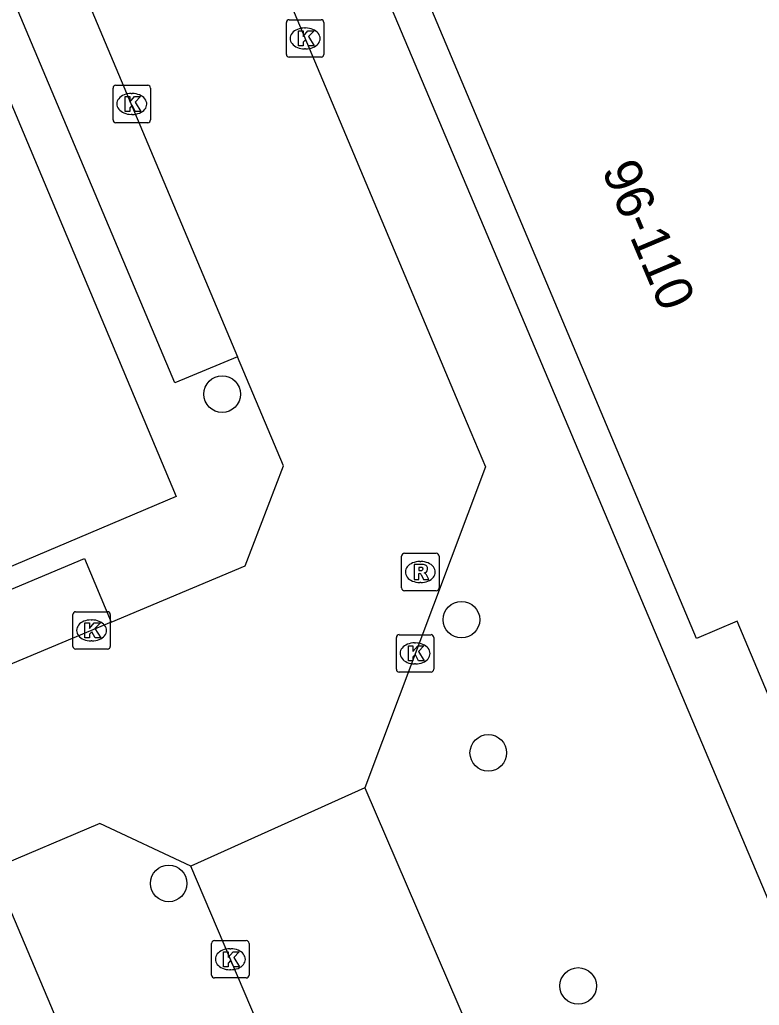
# Model space of a CAD drawing. Extents: x 157767 to 159171, y 387842 to 389425.
# Drawn here: x 158864.69 to 158884.47, y 388333.68 to 388360.03 of the extents above; entities that cross this region are included whole.
import ezdxf

# ---------------------------------------------------------------- set-up
doc = ezdxf.new("R2010")
doc.units = 0
for name, color, linetype in [('IMGEO_Boom', 7, 'Continuous'), ('IMGEO_Kolk', 7, 'Continuous'), ('IMGEO_Pand', 7, 'Continuous'), ('IMGEO_Pand_nummerreeks', 7, 'Continuous'), ('IMGEO_Rijbaan_lokaal_open', 7, 'Continuous'), ('IMGEO_Rioolput', 7, 'Continuous'), ('IMGEO_Voetpad_open', 7, 'Continuous')]:
    doc.layers.add(name, color=color, linetype=linetype)

msp = doc.modelspace()

# ---------------------------------------------------------------- linework, layer by layer
at = {"layer": 'IMGEO_Boom'}
for centre in [(158870.108, 388350.022), (158876.508, 388343.993), (158877.225, 388340.433), (158868.678, 388336.942), (158879.629, 388334.201)]:
    msp.add_circle(centre, 0.489, dxfattribs=at)
at = {"layer": 'IMGEO_Kolk'}
for p, q in [((158871.826, 388359.106), (158871.826, 388359.958)), ((158871.901, 388360.032), (158872.753, 388360.032)), ((158872.827, 388359.958), (158872.827, 388359.106)), ((158872.314, 388359.812), (158872.339, 388359.812)), ((158872.337, 388359.252), (158872.312, 388359.252)), ((158872.753, 388359.032), (158871.901, 388359.032)), ((158867.19, 388357.354), (158867.19, 388358.206)), ((158867.265, 388358.28), (158868.117, 388358.28)), ((158868.191, 388358.206), (158868.191, 388357.354)), ((158867.678, 388358.06), (158867.703, 388358.06)), ((158867.701, 388357.5), (158867.676, 388357.5)), ((158868.117, 388357.28), (158867.265, 388357.28)), ((158866.114, 388343.28), (158866.114, 388344.132)), ((158866.189, 388344.206), (158867.041, 388344.206)), ((158867.115, 388344.132), (158867.115, 388343.28)), ((158866.602, 388343.986), (158866.627, 388343.986)), ((158866.625, 388343.426), (158866.6, 388343.426)), ((158874.767, 388342.666), (158874.767, 388343.518)), ((158874.842, 388343.592), (158875.694, 388343.592)), ((158875.255, 388343.372), (158875.28, 388343.372)), ((158875.768, 388343.518), (158875.768, 388342.666)), ((158867.041, 388343.206), (158866.189, 388343.206)), ((158875.278, 388342.812), (158875.253, 388342.812)), ((158875.694, 388342.592), (158874.842, 388342.592)), ((158869.826, 388334.488), (158869.826, 388335.34)), ((158869.901, 388335.414), (158870.753, 388335.414)), ((158870.314, 388335.194), (158870.339, 388335.194)), ((158870.827, 388335.34), (158870.827, 388334.488)), ((158870.753, 388334.414), (158869.901, 388334.414)), ((158870.337, 388334.634), (158870.312, 388334.634))]:
    msp.add_line(p, q, dxfattribs=at)
for points in [[(158871.826, 388359.106), (158871.826, 388359.958)], [(158871.901, 388360.032), (158872.753, 388360.032)], [(158872.827, 388359.958), (158872.827, 388359.106)], [(158872.147, 388359.732), (158872.27, 388359.732), (158872.27, 388359.581), (158872.4, 388359.732), (158872.564, 388359.732), (158872.418, 388359.581), (158872.571, 388359.332), (158872.419, 388359.332), (158872.334, 388359.496), (158872.27, 388359.429), (158872.27, 388359.332), (158872.147, 388359.332), (158872.147, 388359.732)], [(158872.753, 388359.032), (158871.901, 388359.032)], [(158867.19, 388357.354), (158867.19, 388358.206)], [(158867.265, 388358.28), (158868.117, 388358.28)], [(158868.191, 388358.206), (158868.191, 388357.354)], [(158867.511, 388357.98), (158867.634, 388357.98), (158867.634, 388357.829), (158867.764, 388357.98), (158867.928, 388357.98), (158867.782, 388357.829), (158867.935, 388357.58), (158867.783, 388357.58), (158867.698, 388357.744), (158867.634, 388357.677), (158867.634, 388357.58), (158867.511, 388357.58), (158867.511, 388357.98)], [(158868.117, 388357.28), (158867.265, 388357.28)], [(158866.114, 388343.28), (158866.114, 388344.132)], [(158866.189, 388344.206), (158867.041, 388344.206)], [(158867.115, 388344.132), (158867.115, 388343.28)], [(158866.435, 388343.906), (158866.558, 388343.906), (158866.558, 388343.755), (158866.688, 388343.906), (158866.852, 388343.906), (158866.706, 388343.755), (158866.859, 388343.506), (158866.707, 388343.506), (158866.622, 388343.67), (158866.558, 388343.603), (158866.558, 388343.506), (158866.435, 388343.506), (158866.435, 388343.906)], [(158874.767, 388342.666), (158874.767, 388343.518)], [(158874.842, 388343.592), (158875.694, 388343.592)], [(158875.768, 388343.518), (158875.768, 388342.666)], [(158867.041, 388343.206), (158866.189, 388343.206)], [(158875.088, 388343.292), (158875.211, 388343.292), (158875.211, 388343.141), (158875.341, 388343.292), (158875.505, 388343.292), (158875.359, 388343.141), (158875.512, 388342.892), (158875.36, 388342.892), (158875.275, 388343.056), (158875.211, 388342.989), (158875.211, 388342.892), (158875.088, 388342.892), (158875.088, 388343.292)], [(158875.694, 388342.592), (158874.842, 388342.592)], [(158869.826, 388334.488), (158869.826, 388335.34)], [(158869.901, 388335.414), (158870.753, 388335.414)], [(158870.827, 388335.34), (158870.827, 388334.488)], [(158870.147, 388335.114), (158870.27, 388335.114), (158870.27, 388334.963), (158870.4, 388335.114), (158870.564, 388335.114), (158870.418, 388334.963), (158870.571, 388334.714), (158870.419, 388334.714), (158870.334, 388334.878), (158870.27, 388334.811), (158870.27, 388334.714), (158870.147, 388334.714), (158870.147, 388335.114)], [(158870.753, 388334.414), (158869.901, 388334.414)]]:
    msp.add_lwpolyline(points, dxfattribs=at)
for centre, start, end in [((158871.903, 388359.956), 91.552, 178.448), ((158871.903, 388359.956), 91.552, 178.448), ((158872.751, 388359.956), 1.552, 88.448), ((158872.751, 388359.956), 1.552, 88.448), ((158871.903, 388359.108), 181.552, 268.448), ((158871.903, 388359.108), 181.552, 268.448), ((158872.751, 388359.108), 271.552, 358.448), ((158872.751, 388359.108), 271.552, 358.448), ((158867.267, 388358.204), 91.552, 178.448), ((158867.267, 388358.204), 91.552, 178.448), ((158868.115, 388358.204), 1.552, 88.448), ((158868.115, 388358.204), 1.552, 88.448), ((158867.267, 388357.356), 181.552, 268.448), ((158867.267, 388357.356), 181.552, 268.448), ((158868.115, 388357.356), 271.552, 358.448), ((158868.115, 388357.356), 271.552, 358.448), ((158866.191, 388344.13), 91.552, 178.448), ((158866.191, 388344.13), 91.552, 178.448), ((158867.039, 388344.13), 1.552, 88.448), ((158867.039, 388344.13), 1.552, 88.448), ((158874.844, 388343.516), 91.552, 178.448), ((158874.844, 388343.516), 91.552, 178.448), ((158875.692, 388343.516), 1.552, 88.448), ((158875.692, 388343.516), 1.552, 88.448), ((158866.191, 388343.282), 181.552, 268.448), ((158866.191, 388343.282), 181.552, 268.448), ((158867.039, 388343.282), 271.552, 358.448), ((158867.039, 388343.282), 271.552, 358.448), ((158874.844, 388342.668), 181.552, 268.448), ((158874.844, 388342.668), 181.552, 268.448), ((158875.692, 388342.668), 271.552, 358.448), ((158875.692, 388342.668), 271.552, 358.448), ((158869.903, 388335.338), 91.552, 178.448), ((158869.903, 388335.338), 91.552, 178.448), ((158870.751, 388335.338), 1.552, 88.448), ((158870.751, 388335.338), 1.552, 88.448), ((158869.903, 388334.49), 181.552, 268.448), ((158869.903, 388334.49), 181.552, 268.448), ((158870.751, 388334.49), 271.552, 358.448), ((158870.751, 388334.49), 271.552, 358.448)]:
    msp.add_arc(centre, 0.0765, start, end, dxfattribs=at)
for centre, major_axis, ratio, start_param, end_param in [((158872.313, 388359.532), (-0.387, 0.002), 0.722429, 4.712389, 7.853982), ((158872.338, 388359.532), (-0.39, 0.002), 0.717154, 1.570796, 4.712389), ((158867.677, 388357.78), (-0.387, 0.002), 0.722429, 4.712389, 7.853982), ((158867.702, 388357.78), (-0.39, 0.002), 0.717154, 1.570796, 4.712389), ((158866.601, 388343.706), (-0.387, 0.002), 0.722429, 4.712389, 7.853982), ((158866.626, 388343.706), (-0.39, 0.002), 0.717154, 1.570796, 4.712389), ((158875.254, 388343.092), (-0.387, 0.002), 0.722429, 4.712389, 7.853982), ((158875.279, 388343.092), (-0.39, 0.002), 0.717154, 1.570796, 4.712389), ((158870.313, 388334.914), (-0.387, 0.002), 0.722429, 4.712389, 7.853982), ((158870.338, 388334.914), (-0.39, 0.002), 0.717154, 1.570796, 4.712389)]:
    msp.add_ellipse(centre, major_axis=major_axis, ratio=ratio, start_param=start_param, end_param=end_param, dxfattribs=at)
at = {"layer": 'IMGEO_Pand'}
msp.add_lwpolyline([(158884.156, 388371.409), (158892.445, 388374.91), (158893.417, 388372.607), (158884.594, 388368.881), (158894.893, 388344.493), (158903.706, 388348.215), (158904.663, 388345.949), (158893.85, 388341.383), (158892.902, 388343.626), (158885.364, 388340.443), (158883.881, 388343.954), (158882.795, 388343.494), (158875.426, 388360.972)], dxfattribs=at)
at = {"layer": 'IMGEO_Rijbaan_lokaal_open'}
for points in [[(158856.353, 388384.641), (158870.521, 388351.022)], [(158868.903, 388367.676), (158868.934, 388367.603), (158876.369, 388349.934), (158877.15, 388348.079), (158873.925, 388339.494)], [(158867.141, 388343.929), (158870.725, 388345.429), (158871.751, 388348.104), (158870.521, 388351.022)], [(158867.141, 388343.929), (158844.805, 388334.58)], [(158873.925, 388339.494), (158869.266, 388337.403)], [(158873.925, 388339.494), (158876.988, 388332.381)], [(158869.266, 388337.403), (158866.837, 388338.544), (158863.926, 388337.315)], [(158874.379, 388318.905), (158870.99, 388327.245), (158872.301, 388330.286), (158869.266, 388337.403)]]:
    msp.add_lwpolyline(points, dxfattribs=at)
at = {"layer": 'IMGEO_Rioolput'}
for p, q in [((158874.982, 388345.767), (158875.834, 388345.767)), ((158874.907, 388344.841), (158874.907, 388345.693)), ((158875.395, 388345.547), (158875.42, 388345.547)), ((158875.908, 388345.693), (158875.908, 388344.841)), ((158875.418, 388344.987), (158875.393, 388344.987)), ((158875.834, 388344.767), (158874.982, 388344.767))]:
    msp.add_line(p, q, dxfattribs=at)
for points in [[(158874.982, 388345.767), (158875.834, 388345.767)], [(158874.907, 388344.841), (158874.907, 388345.693)], [(158875.496, 388345.465), (158875.244, 388345.467), (158875.244, 388345.067)], [(158875.908, 388345.693), (158875.908, 388344.841)], [(158875.244, 388345.067), (158875.368, 388345.067), (158875.368, 388345.229), (158875.379, 388345.229)], [(158875.422, 388345.386), (158875.368, 388345.386), (158875.368, 388345.305)], [(158875.368, 388345.305), (158875.42, 388345.305)], [(158875.426, 388345.2), (158875.497, 388345.067), (158875.637, 388345.067), (158875.572, 388345.193)], [(158875.834, 388344.767), (158874.982, 388344.767)]]:
    msp.add_lwpolyline(points, dxfattribs=at)
for centre, radius, start, end in [((158874.984, 388345.691), 0.0765, 91.552, 178.448), ((158874.984, 388345.691), 0.0765, 91.552, 178.448), ((158875.832, 388345.691), 0.0765, 1.552, 88.448), ((158875.832, 388345.691), 0.0765, 1.552, 88.448), ((158875.495, 388345.355), 0.109, 350.3612, 89.416), ((158875.378, 388345.176), 0.0533, 26.0293, 88.6989), ((158875.404, 388345.494), 0.19, 274.7715, 282.9687), ((158875.428, 388345.29), 0.0964, 77.0061, 93.1865), ((158875.442, 388345.347), 0.0378, 276.6634, 79.6772), ((158875.493, 388345.355), 0.112, 277.5842, 350.9817), ((158875.477, 388345.14), 0.108, 29.5134, 73.7905), ((158874.984, 388344.843), 0.0765, 181.552, 268.448), ((158874.984, 388344.843), 0.0765, 181.552, 268.448), ((158875.832, 388344.843), 0.0765, 271.552, 358.448), ((158875.832, 388344.843), 0.0765, 271.552, 358.448)]:
    msp.add_arc(centre, radius, start, end, dxfattribs=at)
for centre, major_axis, ratio, start_param, end_param in [((158875.394, 388345.267), (-0.387, 0.002), 0.722429, 4.712389, 7.853982), ((158875.419, 388345.267), (-0.39, 0.002), 0.717154, 1.570796, 4.712389)]:
    msp.add_ellipse(centre, major_axis=major_axis, ratio=ratio, start_param=start_param, end_param=end_param, dxfattribs=at)
at = {"layer": 'IMGEO_Voetpad_open'}
for points in [[(158838.652, 388419.211), (158868.881, 388347.284), (158853.592, 388340.805), (158843.883, 388336.691), (158834.401, 388332.713), (158827.967, 388330.084)], [(158870.521, 388351.022), (158868.839, 388350.328), (158840.615, 388417.244), (158842.313, 388417.957)], [(158874.528, 388360.59), (158878.652, 388350.839), (158884.896, 388336.062)], [(158844.805, 388334.58), (158844.104, 388336.251), (158866.429, 388345.624), (158867.141, 388343.929)], [(158864.471, 388336.155), (158869.927, 388323.243), (158873.158, 388315.598), (158876.076, 388308.691)]]:
    msp.add_lwpolyline(points, dxfattribs=at)

# ---------------------------------------------------------------- texts
at = {"layer": 'IMGEO_Pand_nummerreeks'}
msp.add_text('96-110', height=1, rotation=292.8608, dxfattribs=at).set_placement((158880.251, 388356.017))

doc.saveas('drawing.dxf')
